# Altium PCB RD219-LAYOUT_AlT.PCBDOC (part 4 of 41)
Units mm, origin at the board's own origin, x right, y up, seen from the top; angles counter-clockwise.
Board outline 209.75 x 159.97 mm, 2 copper layers (TOP, BOTTOM), stack 0 mm thick; 398 components, 199 nets, 1469 pads, 0 vias.
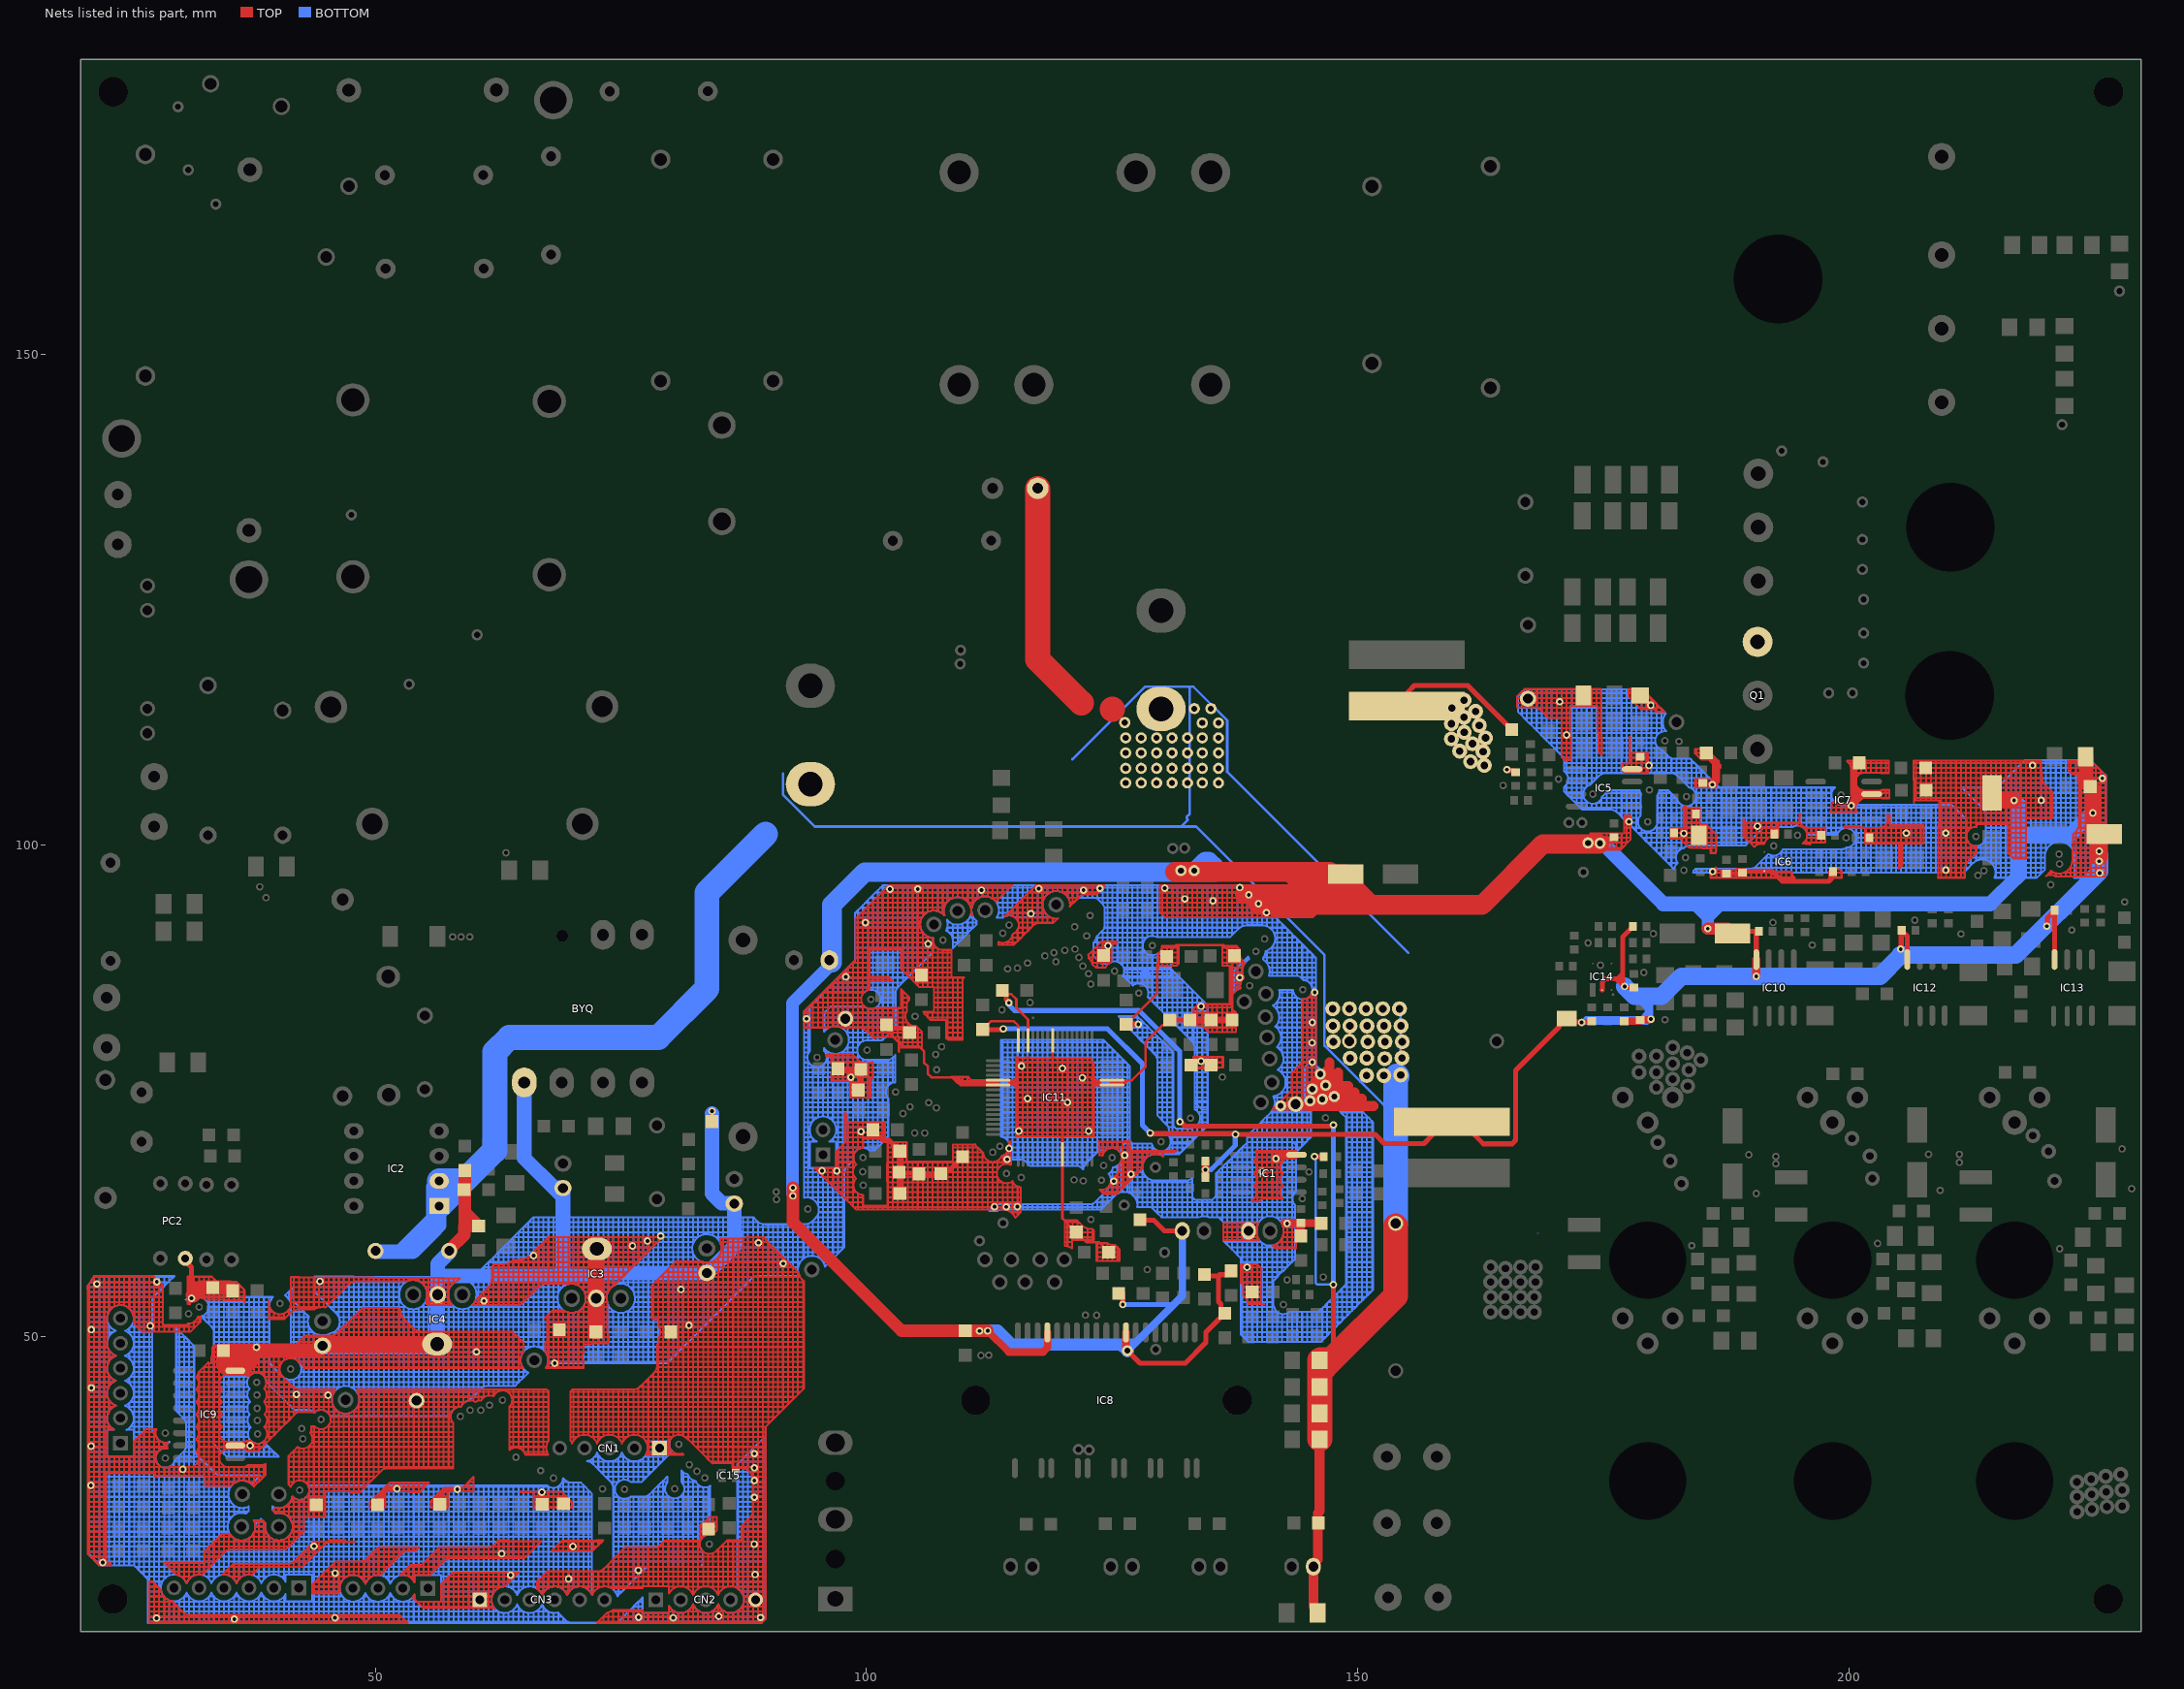
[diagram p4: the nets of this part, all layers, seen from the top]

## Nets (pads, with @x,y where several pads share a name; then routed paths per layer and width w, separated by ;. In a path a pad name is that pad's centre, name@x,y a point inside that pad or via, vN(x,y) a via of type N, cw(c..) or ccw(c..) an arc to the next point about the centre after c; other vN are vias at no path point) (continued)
GND: (continued)
  TOP w0.203: 20.889,33.716 21.397,33.716 ; 20.889,33.716 20.889,34.224 ; 20.889,34.224 pad.@20.889,34.732 ; 20.889,34.224 21.397,34.224 ; pad.@20.889,34.732 pad.@21.397,34.732 ; pad.@20.889,34.732 20.889,35.24 ; 20.889,35.24 20.889,35.748 ; 20.889,35.24 21.397,35.24 ; 20.889,35.748 20.889,36.256 ; 20.889,35.748 21.397,35.748 ; 20.889,36.256 20.889,36.764 ; 20.889,36.256 21.397,36.256 ; 20.889,36.764 20.889,37.272 ; 20.889,36.764 21.397,36.764 ; 20.889,37.272 20.889,37.78 ; 20.889,37.272 21.397,37.272 ; 20.889,37.78 20.889,38.288 ; 20.889,37.78 21.397,37.78 ; 20.889,38.288 pad.@20.889,38.796 ; 20.889,38.288 21.397,38.288 ; pad.@20.889,38.796 pad.@21.397,38.796 ; pad.@20.889,38.796 20.889,39.304 ; 20.889,39.304 20.889,39.812 ; 20.889,39.304 21.397,39.304 ; 20.889,39.812 20.889,40.32 ; 20.889,39.812 21.397,39.812 ; 20.889,40.32 20.889,40.828 ; 20.889,40.32 21.397,40.32 ; 20.889,40.828 20.889,41.336 ; 20.889,40.828 21.397,40.828 ; 20.889,41.336 20.889,41.844 ; 20.889,41.336 21.397,41.336 ; 20.889,41.844 20.889,42.352 ; 20.889,41.844 21.397,41.844 ; 20.889,42.352 20.889,42.86 ; 20.889,42.352 21.397,42.352 ; 20.889,42.86 20.889,43.368 ; 20.889,42.86 21.397,42.86 ; 20.889,43.368 20.889,43.876 ; 20.889,43.368 21.397,43.368 ; 20.889,43.876 21.397,43.876 ; 20.889,43.876 20.889,44.384 ; 20.889,44.384 pad.@20.889,44.892 ; 20.889,44.384 21.397,44.384 ; pad.@20.889,44.892 20.889,45.4 ; pad.@20.889,44.892 pad.@21.397,44.892 ; 20.889,45.4 21.397,45.4 ; 20.889,45.4 20.889,45.908 ; 20.889,45.908 20.889,46.416 ; 20.889,45.908 21.397,45.908 ; 20.889,46.416 20.889,46.924 ; 20.889,46.416 21.397,46.416 ; 20.889,46.924 20.889,47.432 ; 20.889,46.924 21.397,46.924 ; 20.889,47.432 20.889,47.94 ; 20.889,47.432 21.397,47.432 ; 20.889,47.94 21.397,47.94 ; 20.889,47.94 20.889,48.448 ; 20.889,48.448 20.889,48.956 ; 20.889,48.448 21.397,48.448 ; 20.889,48.956 20.889,49.464 ; 20.889,48.956 21.397,48.956 ; 20.889,49.464 21.397,49.464 ; 20.889,49.464 20.889,49.972 ; 20.889,49.972 pad.@20.889,50.48 ; 20.889,49.972 21.397,49.972 ; pad.@20.889,50.48 21.397,50.48 ; pad.@20.889,50.48 pad.@20.889,50.988 ; pad.@20.889,50.988 20.889,51.496 ; pad.@20.889,50.988 21.397,50.988 ; 20.889,51.496 20.889,52.004 ; 20.889,51.496 21.397,51.496 ; 20.889,52.004 21.397,52.004 ; 20.889,52.004 20.889,52.512 ; 20.889,52.512 20.889,53.02 ; 20.889,52.512 21.397,52.512 ; 20.889,53.02 20.889,53.528 ; 20.889,53.02 21.397,53.02 ; 20.889,53.528 21.397,53.528 ; 20.889,53.528 20.889,54.036 ; 20.889,54.036 20.889,54.544 ; 20.889,54.036 21.397,54.036 ; 20.889,54.544 20.889,55.052 ; 20.889,54.544 21.397,54.544 ; 20.889,55.052 20.889,55.369 ; 20.889,55.052 21.397,55.052 ; 20.889,55.369 21.016,55.56 ; 21.016,27.62 21.397,27.62 ; 21.016,27.62 21.397,27.239 ; 21.016,55.56 pad.@21.397,55.56 ; 21.016,55.56 21.441,56.197 22.413,56.191 ; 21.397,27.239 21.397,27.62 ; 21.397,27.239 21.524,27.112 ; 21.397,27.62 21.905,27.62 ; 21.397,27.62 21.397,28.128 ; 21.397,28.128 21.397,28.636 ; 21.397,28.128 21.905,28.128 ; 21.397,28.636 21.397,29.144 ; 21.397,28.636 21.905,28.636 ; 21.397,29.144 21.905,29.144 ; 21.397,29.144 21.397,29.652 ; 21.397,29.652 21.905,29.652 ; 21.397,29.652 21.397,30.16 ; 21.397,30.16 21.397,30.668 ; 21.397,30.16 21.905,30.16 ; 21.397,30.668 21.397,31.176 ; 21.397,30.668 21.905,30.668 ; 21.397,31.176 21.397,31.684 ; 21.397,31.176 21.905,31.176 ; 21.397,31.684 21.905,31.684 ; 21.397,31.684 21.397,32.192 ; 21.397,32.192 21.397,32.7 ; 21.397,32.192 21.905,32.192 ; 21.397,32.7 21.397,33.208 ; 21.397,32.7 21.905,32.7 ; 21.397,33.208 21.397,33.716 ; 21.397,33.208 21.905,33.208 ; 21.397,33.716 21.905,33.716 ; 21.397,33.716 21.397,34.224 ; 21.397,34.224 pad.@21.397,34.732 ; 21.397,34.224 21.905,34.224 ; pad.@21.397,34.732 21.905,34.732 ; pad.@21.397,34.732 21.397,35.24 ; 21.397,35.24 21.905,35.24 ; 21.397,35.24 21.397,35.748 ; 21.397,35.748 21.397,36.256 ; 21.397,35.748 21.905,35.748 ; 21.397,36.256 21.397,36.764 ; 21.397,36.256 21.905,36.256 ; 21.397,36.764 21.397,37.272 ; 21.397,36.764 21.905,36.764 ; 21.397,37.272 21.397,37.78 ; 21.397,37.272 21.905,37.272 ; 21.397,37.78 21.397,38.288 ; 21.397,37.78 21.905,37.78 ; 21.397,38.288 pad.@21.397,38.796 ; 21.397,38.288 21.905,38.288 ; pad.@21.397,38.796 21.905,38.796 ; pad.@21.397,38.796 21.397,39.304 ; 21.397,39.304 21.397,39.812 ; 21.397,39.304 21.905,39.304 ; 21.397,39.812 21.397,40.32 ; 21.397,39.812 21.905,39.812 ; 21.397,40.32 21.397,40.828 ; 21.397,40.32 21.905,40.32 ; 21.397,40.828 21.397,41.336 ; 21.397,40.828 21.905,40.828 ; 21.397,41.336 21.397,41.844 ; 21.397,41.336 21.905,41.336 ; 21.397,41.844 21.397,42.352 ; 21.397,41.844 21.905,41.844 ; 21.397,42.352 21.397,42.86 ; 21.397,42.352 21.905,42.352 ; 21.397,42.86 21.397,43.368 ; 21.397,42.86 21.905,42.86 ; 21.397,43.368 21.397,43.876 ; 21.397,43.368 21.905,43.368 ; 21.397,43.876 21.905,43.876 ; 21.397,43.876 21.397,44.384 ; 21.397,44.384 21.905,44.384 ; 21.397,44.384 pad.@21.397,44.892 ; pad.@21.397,44.892 21.397,45.4 ; pad.@21.397,44.892 21.905,44.892 ; 21.397,45.4 21.905,45.4 ; 21.397,45.4 21.397,45.908 ; 21.397,45.908 21.397,46.416 ; 21.397,45.908 21.905,45.908 ; 21.397,46.416 21.397,46.924 ; 21.397,46.416 21.905,46.416 ; 21.397,46.924 21.397,47.432 ; 21.397,46.924 21.905,46.924 ; 21.397,47.432 21.397,47.94 ; 21.397,47.432 21.905,47.432 ; 21.397,47.94 21.905,47.94 ; 21.397,47.94 21.397,48.448 ; 21.397,48.448 21.397,48.956 ; 21.397,48.448 21.905,48.448 ; 21.397,48.956 21.397,49.464 ; 21.397,48.956 21.905,48.956 ; 21.397,49.464 21.905,49.464 ; 21.397,49.464 21.397,49.972 ; 21.397,49.972 21.397,50.48 ; 21.397,49.972 21.905,49.972 ; 21.397,50.48 21.905,50.48 ; 21.397,50.48 21.397,50.988 ; 21.397,50.988 21.397,51.496 ; 21.397,50.988 21.905,50.988 ; 21.397,51.496 21.397,52.004 ; 21.397,51.496 21.905,51.496 ; 21.397,52.004 21.905,52.004 ; 21.397,52.004 21.397,52.512 ; 21.397,52.512 21.397,53.02 ; 21.397,52.512 21.905,52.512 ; 21.397,53.02 21.397,53.528 ; 21.397,53.02 21.905,53.02 ; 21.397,53.528 21.905,53.528 ; 21.397,53.528 21.397,54.036 ; 21.397,54.036 21.397,54.544 ; 21.397,54.036 21.905,54.036 ; 21.397,54.544 21.397,55.052 ; 21.397,54.544 21.905,54.544 ; 21.397,55.052 pad.@21.397,55.56 ; 21.397,55.052 21.905,55.052 ; pad.@21.397,55.56 21.397,56.068 ; pad.@21.397,55.56 pad.@21.905,55.56 ; 21.397,56.068 21.905,56.068 ; 21.524,27.112 pad.@21.905,27.112 ; 21.524,27.112 21.905,26.731 ; 21.905,26.731 pad.@22.413,26.731 ; 21.905,26.731 pad.@21.905,27.112 ; pad.@21.905,27.112 21.905,27.62 ; pad.@21.905,27.112 pad.@22.413,27.112 ; 21.905,27.62 22.413,27.62 ; 21.905,27.62 21.905,28.128 ; 21.905,28.128 21.905,28.636 ; 21.905,28.128 22.413,28.128 ; 21.905,28.636 21.905,29.144 ; 21.905,28.636 22.413,28.636 ; 21.905,29.144 21.905,29.652 ; 21.905,29.144 22.413,29.144 ; 21.905,29.652 21.905,30.16 ; 21.905,29.652 22.413,29.652 ; 21.905,30.16 21.905,30.668 ; 21.905,30.16 22.413,30.16 ; 21.905,30.668 21.905,31.176 ; 21.905,30.668 22.413,30.668 ; 21.905,31.176 21.905,31.684 ; 21.905,31.176 22.413,31.176 ; 21.905,31.684 21.905,32.192 ; 21.905,31.684 22.413,31.684 ; 21.905,32.192 21.905,32.7 ; 21.905,32.192 22.413,32.192 ; 21.905,32.7 21.905,33.208 ; 21.905,32.7 22.413,32.7 ; 21.905,33.208 21.905,33.716 ; 21.905,33.208 22.413,33.208 ; 21.905,33.716 22.413,33.716 ; 21.905,33.716 21.905,34.224 ; 21.905,34.224 21.905,34.732 ; 21.905,34.224 22.413,34.224 ; 21.905,34.732 22.413,34.732 ; 21.905,34.732 21.905,35.24 ; 21.905,35.24 22.413,35.24 ; 21.905,35.24 21.905,35.748 ; 21.905,35.748 21.905,36.256 ; 21.905,35.748 22.413,35.748 ; 21.905,36.256 21.905,36.764 ; 21.905,36.256 22.413,36.256 ; 21.905,36.764 21.905,37.272 ; 21.905,36.764 22.413,36.764 ; 21.905,37.272 21.905,37.78 ; 21.905,37.272 22.413,37.272 ; 21.905,37.78 21.905,38.288 ; 21.905,37.78 22.413,37.78 ; 21.905,38.288 21.905,38.796 ; 21.905,38.288 22.413,38.288 ; 21.905,38.796 21.905,39.304 ; 21.905,38.796 22.413,38.796 ; 21.905,39.304 21.905,39.812 ; 21.905,39.304 22.413,39.304 ; 21.905,39.812 21.905,40.32 ; 21.905,39.812 22.413,39.812 ; 21.905,40.32 21.905,40.828 ; 21.905,40.32 22.413,40.32 ; 21.905,40.828 21.905,41.336 ; 21.905,40.828 22.413,40.828 ; 21.905,41.336 21.905,41.844 ; 21.905,41.336 22.413,41.336 ; 21.905,41.844 21.905,42.352 ; 21.905,41.844 22.413,41.844 ; 21.905,42.352 21.905,42.86 ; 21.905,42.352 22.413,42.352 ; 21.905,42.86 21.905,43.368 ; 21.905,42.86 22.413,42.86 ; 21.905,43.368 21.905,43.876 ; 21.905,43.368 22.413,43.368 ; 21.905,43.876 22.413,43.876 ; 21.905,43.876 21.905,44.384 ; 21.905,44.384 22.413,44.384 ; 21.905,44.384 21.905,44.892 ; 21.905,44.892 21.905,45.4 ; 21.905,44.892 22.413,44.892 ; 21.905,45.4 21.905,45.908 ; 21.905,45.4 22.413,45.4 ; 21.905,45.908 21.905,46.416 ; 21.905,45.908 22.413,45.908 ; 21.905,46.416 21.905,46.924 ; 21.905,46.416 22.413,46.416 ; 21.905,46.924 21.905,47.432 ; 21.905,46.924 22.413,46.924 ; 21.905,47.432 21.905,47.94 ; 21.905,47.432 22.413,47.432 ; 21.905,47.94 22.413,47.94 ; 21.905,47.94 21.905,48.448 ; 21.905,48.448 21.905,48.956 ; 21.905,48.448 22.413,48.448 ; 21.905,48.956 21.905,49.464 ; 21.905,48.956 22.413,48.956 ; 21.905,49.464 22.413,49.464 ; 21.905,49.464 21.905,49.972 ; 21.905,49.972 21.905,50.48 ; 21.905,49.972 22.413,49.972 ; 21.905,50.48 21.905,50.988 ; 21.905,50.48 22.413,50.48 ; 21.905,50.988 21.905,51.496 ; 21.905,50.988 22.413,50.988 ; 21.905,51.496 21.905,52.004 ; 21.905,51.496 22.413,51.496 ; 21.905,52.004 22.413,52.004 ; 21.905,52.004 21.905,52.512 ; 21.905,52.512 21.905,53.02 ; 21.905,52.512 22.413,52.512 ; 21.905,53.02 21.905,53.528 ; 21.905,53.02 22.413,53.02 ; 21.905,53.528 22.413,53.528 ; 21.905,53.528 21.905,54.036 ; 21.905,54.036 21.905,54.544 ; 21.905,54.036 22.413,54.036 ; 21.905,54.544 21.905,55.052 ; 21.905,54.544 22.413,54.544 ; 21.905,55.052 22.413,55.052 ; 21.905,55.052 pad.@21.905,55.56 ; pad.@21.905,55.56 21.905,56.068 ; pad.@21.905,55.56 22.413,55.56 ; 21.905,56.068 22.413,56.068 ; pad.@22.413,26.731 22.921,26.731 ; pad.@22.413,26.731 pad.@22.413,27.112 ; pad.@22.413,27.112 22.413,27.62 ; pad.@22.413,27.112 pad.@22.609,27.112 ; 22.413,27.62 22.609,27.62 ; 22.413,27.62 22.413,28.128 ; 22.413,28.128 22.413,28.636 ; 22.413,28.128 22.609,28.128 ; 22.413,28.636 22.413,29.144 ; 22.413,28.636 22.609,28.636 ; 22.413,29.144 22.413,29.652 ; 22.413,29.144 22.609,29.144 ; 22.413,29.652 22.413,30.16 ; 22.413,29.652 22.609,29.652 ; 22.413,30.16 22.413,30.668 ; 22.413,30.16 22.609,30.16 ; 22.413,30.668 22.413,31.176 ; 22.413,30.668 22.609,30.668 ; 22.413,31.176 22.413,31.684 ; 22.413,31.176 22.609,31.176 ; 22.413,31.684 22.413,32.192 ; 22.413,31.684 22.609,31.684 ; 22.413,32.192 22.413,32.7 ; 22.413,32.192 22.609,32.192 ; 22.413,32.7 22.413,33.208 ; 22.413,32.7 22.609,32.7 ; 22.413,33.208 22.413,33.716 ; 22.413,33.208 22.609,33.208 ; 22.413,33.716 22.609,33.716 ; 22.413,33.716 22.413,34.224 ; 22.413,34.224 22.413,34.732 ; 22.413,34.224 22.609,34.224 ; 22.413,34.732 22.413,35.24 ; 22.413,34.732 22.577,34.732 ; 22.413,35.24 22.413,35.748 ; 22.413,35.24 22.609,35.24 ; 22.413,35.748 22.413,36.256 ; 22.413,35.748 22.609,35.748 ; 22.413,36.256 22.413,36.764 ; 22.413,36.256 22.921,36.256 ; 22.413,36.764 22.413,37.272 ; 22.413,36.764 22.921,36.764 ; 22.413,37.272 22.413,37.78 ; 22.413,37.272 22.921,37.272 ; 22.413,37.78 22.413,38.288 ; 22.413,37.78 22.921,37.78 ; 22.413,38.288 22.413,38.796 ; 22.413,38.288 22.712,38.288 ; 22.413,38.796 22.413,39.304 ; 22.413,38.796 22.712,38.796 ; 22.413,39.304 22.413,39.812 ; 22.413,39.304 22.712,39.304 ; 22.413,39.812 22.413,40.32 ; 22.413,39.812 22.712,39.812 ; 22.413,40.32 22.413,40.828 ; 22.413,40.32 22.712,40.32 ; 22.413,40.828 22.413,41.336 ; 22.413,40.828 22.921,40.828 ; 22.413,41.336 22.413,41.844 ; 22.413,41.336 22.767,41.336 ; 22.413,41.844 22.413,42.352 ; 22.413,41.844 22.718,41.844 ; 22.413,42.352 22.413,42.86 ; 22.413,42.352 22.871,42.352 ; 22.413,42.86 22.413,43.368 ; 22.413,42.86 22.921,42.86 ; 22.413,43.368 22.413,43.876 ; 22.413,43.368 22.921,43.368 ; 22.413,43.876 22.413,44.384 ; 22.413,43.876 22.765,43.876 ; 22.413,44.384 22.413,44.892 ; 22.413,44.384 22.718,44.384 ; 22.413,44.892 22.413,45.4 ; 22.413,44.892 22.871,44.892 ; 22.413,45.4 22.413,45.908 ; 22.413,45.4 22.921,45.4 ; 22.413,45.908 22.413,46.416 ; 22.413,45.908 22.921,45.908 ; 22.413,46.416 22.413,46.924 ; 22.413,46.416 22.767,46.416 ; 22.413,46.924 22.413,47.432 ; 22.413,46.924 22.718,46.924 ; 22.413,47.432 22.413,47.94 ; 22.413,47.432 22.871,47.432 ; 22.413,47.94 22.921,47.94 ; 22.413,47.94 22.413,48.448 ; 22.413,48.448 22.413,48.956 ; 22.413,48.448 22.921,48.448 ; 22.413,48.956 22.413,49.464 ; 22.413,48.956 22.767,48.956 ; 22.413,49.464 22.413,49.972 ; 22.413,49.464 22.712,49.464 ; 22.413,49.972 22.413,50.48 ; 22.413,49.972 22.712,49.972 ; 22.413,50.48 22.413,50.988 ; 22.413,50.48 22.712,50.48 ; 22.413,50.988 22.413,51.496 ; 22.413,50.988 22.712,50.988 ; 22.413,51.496 22.413,52.004 ; 22.413,51.496 22.712,51.496 ; 22.413,52.004 22.413,52.512 ; 22.413,52.004 22.718,52.004 ; 22.413,52.512 22.413,53.02 ; 22.413,52.512 22.871,52.512 ; 22.413,53.02 22.413,53.528 ; 22.413,53.02 22.921,53.02 ; 22.413,53.528 22.921,53.528 ; 22.413,53.528 22.413,54.036 ; 22.413,54.036 22.413,54.544 ; 22.413,54.036 22.921,54.036 ; 22.413,54.544 22.413,55.052 ; 22.413,54.544 22.921,54.544 ; 22.413,55.052 22.413,55.56 ; 22.413,55.052 22.921,55.052 ; 22.413,55.56 22.921,55.56 ; 22.413,55.56 22.413,56.068 ; 22.413,56.068 22.921,56.068 ; 22.413,56.068 22.413,56.191 ; 22.413,56.191 22.921,56.187 ; 22.577,34.732 cw(c23.429,34.808) 22.609,35.053 ; pad.@22.609,27.112 22.609,27.62 ; pad.@22.609,27.112 22.609,27.003 22.921,27.003 ; 22.609,27.62 22.609,28.128 ; 22.609,28.128 22.609,28.636 ; 22.609,28.636 22.609,29.144 ; 22.609,29.144 22.609,29.652 ; 22.609,29.652 22.609,30.16 ; 22.609,30.16 22.609,30.668 ; 22.609,30.668 22.609,31.176 ; 22.609,31.176 22.609,31.684 ; 22.609,31.684 22.609,32.192 ; 22.609,32.192 22.609,32.7 ; 22.609,32.7 22.609,33.208 ; 22.609,33.208 22.609,33.716 ; 22.609,33.716 22.609,34.224 ; 22.609,35.053 22.609,35.24 ; 22.609,35.24 22.609,35.748 ; 22.609,35.748 22.609,36.111 22.921,36.111 ; 22.712,38.288 22.712,38.796 ; 22.712,38.288 22.712,37.825 22.921,37.825 ; 22.712,38.796 22.712,39.304 ; 22.712,39.304 22.712,39.812 ; 22.712,39.812 22.712,40.32 ; 22.712,40.32 22.712,40.529 22.921,40.529 ; 22.712,49.464 22.712,49.972 ; 22.712,49.972 22.712,50.48 ; 22.712,50.48 22.712,50.988 ; 22.712,50.988 22.712,51.496 ; 22.714,44.315 ccw(c23.429,44.177) 22.765,43.876 ; 22.714,44.315 cw(c24.064,44.257) 22.718,44.384 ; 22.718,41.844 ccw(c24.064,41.717) 22.718,41.835 ccw(c24.064,41.717) 22.767,41.336 ; 22.718,41.844 cw(c24.064,41.717) 22.871,42.352 ; 22.718,44.384 cw(c24.064,44.257) 22.871,44.892 ; 22.718,46.924 ccw(c24.064,46.797) 22.718,46.915 ccw(c24.064,46.797) 22.767,46.416 ; 22.718,46.924 cw(c24.064,46.797) 22.871,47.432 ; 22.718,52.004 ccw(c24.064,51.877) 22.712,51.877 cw(c24.064,51.877) 22.718,52.004 ; 22.718,52.004 cw(c24.064,51.877) 22.871,52.512 ; 22.718,52.004 cw(c24.064,51.877) 22.871,52.512 ; 22.765,48.964 cw(c24.064,49.337) 22.712,49.337 ccw(c24.064,49.337) 22.765,48.964 ; 22.765,48.964 ccw(c24.064,49.337) 22.767,48.956 ; 22.765,48.964 ccw(c24.064,49.337) 22.767,48.956 ; 22.767,41.336 ccw(c24.064,41.717) 22.918,41.001 ccw(c24.064,41.717) 22.921,40.996 ; 22.767,46.416 ccw(c24.064,46.797) 22.918,46.081 ccw(c24.064,46.797) 22.921,46.076 ; 22.767,48.956 ccw(c24.064,49.337) 22.918,48.621 ; 22.767,48.956 ccw(c24.064,49.337) 22.918,48.621 ; 22.871,42.352 cw(c24.064,41.717) 22.918,42.433 cw(c24.064,41.717) 22.921,42.438 ; 22.871,44.892 cw(c24.064,44.257) 22.918,44.973 cw(c24.064,44.257) 22.921,44.978 ; 22.871,47.432 cw(c24.064,46.797) 22.918,47.513 cw(c24.064,46.797) 22.921,47.518 ; 22.871,52.512 cw(c24.064,51.877) 22.918,52.593 ccw(c24.064,51.877) 22.871,52.512 ; 22.918,48.621 ccw(c24.064,49.337) 22.921,48.616 ; 22.918,48.621 ccw(c24.064,49.337) 22.921,48.616 ; 22.921,26.731 22.921,27.003 ; 22.921,26.731 23.152,26.731 ; 22.921,27.003 22.991,27.003 ; 22.921,36.111 22.921,36.256 ; 22.921,36.111 23.429,36.111 ; 22.921,36.256 22.921,36.764 ; 22.921,36.256 23.429,36.256 ; 22.921,36.764 22.921,37.272 ; 22.921,36.764 23.429,36.764 ; 22.921,37.272 22.921,37.78 ; 22.921,37.272 23.429,37.272 ; 22.921,37.78 22.921,37.825 ; 22.921,37.78 23.429,37.78 ; 22.921,37.825 23.429,37.825 ; 22.921,40.529 22.921,40.828 ; 22.921,40.828 23.046,40.828 ; 22.921,40.828 22.921,40.996 ; 22.921,40.996 ccw(c24.064,41.717) 23.044,40.83 ccw(c24.064,41.717) 23.046,40.828 ; 22.921,42.438 cw(c24.064,41.717) 23.343,42.86 ; 22.921,42.438 22.921,42.86 ; 22.921,42.86 22.921,43.368 ; 22.921,42.86 23.343,42.86 ; 22.921,43.368 23.046,43.368 ; 22.921,43.368 22.921,43.536 ; 22.921,43.536 ccw(c24.064,44.257) 23.044,43.37 ccw(c24.064,44.257) 23.046,43.368 ; 22.921,44.978 cw(c24.064,44.257) 23.343,45.4 ; 22.921,44.978 22.921,45.4 ; 22.921,45.4 22.921,45.908 ; 22.921,45.4 23.343,45.4 ; 22.921,45.908 22.921,46.076 ; 22.921,45.908 23.046,45.908 ; 22.921,46.076 ccw(c24.064,46.797) 23.044,45.91 ccw(c24.064,46.797) 23.046,45.908 ; 22.921,47.518 cw(c24.064,46.797) 23.343,47.94 ; 22.921,47.518 22.921,47.94 ; 22.921,47.94 22.921,48.448 ; 22.921,47.94 23.343,47.94 ; 22.921,48.448 23.046,48.448 ; 22.921,48.448 22.921,48.616 ; 22.921,48.616 ccw(c24.064,49.337) 23.044,48.45 ; 22.921,48.616 ccw(c24.064,49.337) 23.044,48.45 ; 22.921,53.02 22.921,53.528 ; 22.921,53.02 23.343,53.02 ; 22.921,53.528 22.921,54.036 ; 22.921,53.528 23.429,53.528 ; 22.921,54.036 22.921,54.544 ; 22.921,54.036 23.429,54.036 ; 22.921,54.544 22.921,55.052 ; 22.921,54.544 23.429,54.544 ; 22.921,55.052 22.921,55.56 ; 22.921,55.052 23.429,55.052 ; 22.921,55.56 22.921,56.068 ; 22.921,55.56 23.429,55.56 ; 22.921,56.068 22.921,56.187 ; 22.921,56.068 23.429,56.068 ; 22.921,56.187 23.429,56.184 ; 22.991,27.003 ccw(c24.011,27.421) 23.152,26.731 ; 22.991,27.003 ccw(c24.011,27.421) 23.152,26.731 ; 22.991,27.003 cw(c24.011,27.421) 22.989,27.008 ccw(c24.011,27.421) 22.991,27.003 ; 23.044,48.45 ccw(c24.064,49.337) 23.046,48.448 ; 23.044,48.45 ccw(c24.064,49.337) 23.046,48.448 ; 23.046,43.368 ccw(c24.064,44.257) 23.429,43.064 ; 23.046,45.908 ccw(c24.064,46.797) 23.429,45.604 ; 23.046,48.448 ccw(c24.064,49.337) 23.429,48.144 ; 23.046,48.448 ccw(c24.064,49.337) 23.429,48.144 ; 23.152,26.731 ccw(c24.011,27.421) 23.155,26.728 cw(c24.011,27.421) 23.152,26.731 ; 23.343,42.86 cw(c24.064,41.717) 23.429,42.91 ; 23.343,45.4 cw(c24.064,44.257) 23.429,45.45 ; 23.343,47.94 cw(c24.064,46.797) 23.429,47.99 ; 23.343,53.02 ccw(c24.064,51.877) 22.93,52.613 cw(c24.064,51.877) 23.343,53.02 ; 23.343,53.02 cw(c24.064,51.877) 23.348,53.023 ; 23.343,53.02 cw(c24.064,51.877) 23.348,53.023 ; 23.348,53.023 cw(c24.064,51.877) 23.429,53.07 ; 23.348,53.023 cw(c24.064,51.877) 23.429,53.07 ; 23.429,36.111 23.429,36.256 ; 23.429,36.111 23.937,36.111 ; 23.429,36.256 23.429,36.764 ; 23.429,36.256 23.937,36.256 ; 23.429,36.764 23.429,37.272 ; 23.429,36.764 23.937,36.764 ; 23.429,37.272 23.429,37.78 ; 23.429,37.272 23.937,37.272 ; 23.429,37.78 23.429,37.825 ; 23.429,37.78 23.937,37.78 ; 23.429,37.825 23.937,37.825 ; 23.429,42.91 cw(c24.064,41.717) 23.601,42.987 cw(c24.064,44.257) 23.429,43.064 ; 23.429,42.91 23.429,43.064 ; 23.429,45.45 cw(c24.064,44.257) 23.601,45.527 cw(c24.064,46.797) 23.429,45.604 ; 23.429,45.45 23.429,45.604 ; 23.429,47.99 cw(c24.064,46.797) 23.601,48.067 ; 23.429,47.99 23.429,48.144 ; 23.429,48.144 ccw(c24.064,49.337) 23.601,48.067 ; 23.429,48.144 ccw(c24.064,49.337) 23.601,48.067 ; 23.429,53.07 cw(c24.064,51.877) 23.937,53.223 ; 23.429,53.07 cw(c24.064,51.877) 23.937,53.223 ; 23.429,53.07 23.429,53.528 ; 23.429,53.528 23.429,54.036 ; 23.429,53.528 23.937,53.528 ; 23.429,54.036 23.429,54.544 ; 23.429,54.036 23.937,54.036 ; 23.429,54.544 23.429,55.052 ; 23.429,54.544 23.937,54.544 ; 23.429,55.052 23.429,55.56 ; 23.429,55.052 23.937,55.052 ; 23.429,55.56 23.429,56.068 ; 23.429,55.56 23.937,55.56 ; 23.429,56.068 23.429,56.184 ; 23.429,56.068 23.937,56.068 ; 23.429,56.184 23.937,56.181 ; 23.937,36.111 23.937,36.256 ; 23.937,36.111 24.445,36.111 ; 23.937,36.256 23.937,36.764 ; 23.937,36.256 24.445,36.256 ; 23.937,36.764 23.937,37.272 ; 23.937,36.764 24.445,36.764 ; 23.937,37.272 23.937,37.78 ; 23.937,37.272 24.445,37.272 ; 23.937,37.78 23.937,37.825 ; 23.937,37.78 24.445,37.78 ; 23.937,37.825 24.445,37.825 ; 23.937,53.223 ccw(c24.064,51.877) 23.923,53.221 cw(c24.064,51.877) 23.937,53.223 ; 23.937,53.223 cw(c24.064,51.877) 23.946,53.223 ccw(c24.064,51.877) 23.937,53.223 ; 23.937,53.223 cw(c24.064,51.877) 24.437,53.176 ; 23.937,53.223 cw(c24.064,51.877) 24.437,53.176 ; 23.937,53.223 23.937,53.528 ; 23.937,53.528 23.937,54.036 ; 23.937,53.528 24.445,53.528 ; 23.937,54.036 23.937,54.544 ; 23.937,54.036 24.445,54.036 ; 23.937,54.544 23.937,55.052 ; 23.937,54.544 24.445,54.544 ; 23.937,55.052 23.937,55.56 ; 23.937,55.052 24.445,55.052 ; 23.937,55.56 23.937,56.068 ; 23.937,55.56 24.445,55.56 ; 23.937,56.068 23.937,56.181 ; 23.937,56.068 24.445,56.068 ; 23.937,56.181 24.445,56.177 ; 24.437,53.176 cw(c24.064,51.877) 24.445,53.174 ; 24.437,53.176 cw(c24.064,51.877) 24.445,53.174 ; 24.445,36.111 24.953,36.111 ; 24.445,36.111 24.445,36.256 ; 24.445,36.256 24.445,36.764 ; 24.445,36.256 24.953,36.256 ; 24.445,36.764 24.445,37.272 ; 24.445,36.764 24.953,36.764 ; 24.445,37.272 24.445,37.78 ; 24.445,37.272 24.953,37.272 ; 24.445,37.78 24.445,37.825 ; 24.445,37.78 24.953,37.78 ; 24.445,37.825 24.953,37.825 ; 24.445,53.174 cw(c24.064,51.877) 24.78,53.023 ; 24.445,53.174 cw(c24.064,51.877) 24.78,53.023 ; 24.445,53.174 24.445,53.528 ; 24.445,53.528 24.445,54.036 ; 24.445,53.528 24.953,53.528 ; 24.445,54.036 24.445,54.544 ; 24.445,54.036 24.953,54.036 ; 24.445,54.544 24.445,55.052 ; 24.445,54.544 24.953,54.544 ; 24.445,55.052 24.445,55.56 ; 24.445,55.052 24.953,55.052 ; 24.445,55.56 24.445,56.068 ; 24.445,55.56 24.953,55.56 ; 24.445,56.068 24.445,56.177 ; 24.445,56.068 24.953,56.068 ; 24.445,56.177 24.953,56.174 ; 24.78,53.023 cw(c24.064,51.877) 24.785,53.02 ; 24.78,53.023 cw(c24.064,51.877) 24.785,53.02 ; 24.785,53.02 cw(c24.064,51.877) 24.951,52.897 ; 24.785,53.02 cw(c24.064,51.877) 24.951,52.897 ; 24.785,53.02 24.953,53.02 ; 24.951,52.897 cw(c24.064,51.877) 24.953,52.895 ; 24.951,52.897 cw(c24.064,51.877) 24.953,52.895 ; 24.953,36.111 24.953,36.256 ; 24.953,36.256 24.953,36.764 ; 24.953,36.256 25.461,36.256 ; 24.953,36.764 24.953,37.272 ; 24.953,36.764 25.461,36.764 ; 24.953,37.272 24.953,37.78 ; 24.953,37.272 25.461,37.272 ; 24.953,37.78 24.953,37.825 ; 24.953,37.78 25.461,37.78 ; 24.953,37.825 25.416,37.825 25.416,38.288 ; 24.953,52.895 cw(c24.064,51.877) 25.257,52.512 ; 24.953,52.895 cw(c24.064,51.877) 25.257,52.512 ; 24.953,52.895 24.953,53.02 ; 24.953,53.02 24.953,53.528 ; 24.953,53.02 25.461,53.02 ; 24.953,53.528 25.461,53.528 ; 24.953,53.528 24.953,54.036 ; 24.953,54.036 24.953,54.544 ; 24.953,54.036 25.461,54.036 ; 24.953,54.544 24.953,55.052 ; 24.953,54.544 25.461,54.544 ; 24.953,55.052 25.461,55.052 ; 24.953,55.052 24.953,55.56 ; 24.953,55.56 25.461,55.56 ; 24.953,55.56 24.953,56.068 ; 24.953,56.068 25.461,56.068 ; 24.953,56.068 24.953,56.174 ; 24.953,56.174 25.969,56.167 ; 25.257,52.512 cw(c24.064,51.877) 25.41,52.004 ; 25.257,52.512 cw(c24.064,51.877) 25.41,52.004 ; 25.257,52.512 25.461,52.512 ; 25.41,52.004 cw(c24.064,51.877) 25.416,51.877 ccw(c24.064,51.877) 25.41,52.004 ; 25.41,52.004 25.461,52.004 ; 25.416,38.288 25.416,38.796 ; 25.416,38.288 25.461,38.288 ; 25.416,38.796 25.461,38.796 ; 25.416,38.796 25.416,39.304 ; 25.416,39.304 25.461,39.304 ; 25.416,39.304 25.416,39.319 25.461,39.364 ; 25.416,51.496 25.461,51.496 ; 25.416,51.496 25.416,51.388 25.461,51.342 ; 25.461,36.111 25.969,36.111 ; 25.461,36.111 25.461,36.256 ; 25.461,36.256 25.461,36.764 ; 25.461,36.256 25.969,36.256 ; 25.461,36.764 25.461,37.272 ; 25.461,36.764 25.969,36.764 ; 25.461,37.272 25.461,37.78 ; 25.461,37.272 25.969,37.272 ; 25.461,37.78 25.461,38.288 ; 25.461,37.78 25.969,37.78 ; 25.461,38.288 25.461,38.796 ; 25.461,38.288 25.969,38.288 ; 25.461,38.796 25.969,38.796 ; 25.461,38.796 25.461,39.304 ; 25.461,39.304 25.969,39.304 ; 25.461,39.304 25.461,39.364 ; 25.461,39.364 25.909,39.812 ; 25.461,51.342 25.461,51.496 ; 25.461,51.342 25.815,50.988 ; 25.461,51.496 25.969,51.496 ; 25.461,51.496 25.461,52.004 ; 25.461,52.004 25.461,52.512 ; 25.461,52.004 25.969,52.004 ; 25.461,52.512 25.461,53.02 ; 25.461,52.512 25.969,52.512 ; 25.461,53.02 25.461,53.528 ; 25.461,53.02 25.969,53.02 ; 25.461,53.528 25.969,53.528 ; 25.461,53.528 25.461,54.036 ; 25.461,54.036 25.461,54.544 ; 25.461,54.036 25.969,54.036 ; 25.461,54.544 25.461,55.052 ; 25.461,54.544 25.969,54.544 ; 25.461,55.052 25.461,55.56 ; 25.461,55.052 25.969,55.052 ; 25.461,55.56 25.969,55.56 ; 25.461,55.56 25.461,56.068 ; 25.461,56.068 25.969,56.068 ; 25.815,50.988 25.969,50.988 ; 25.815,50.988 25.969,50.834 ; 25.909,39.812 25.969,39.812 ; 25.909,39.812 25.969,39.872 ; 25.969,36.111 25.969,36.256 ; 25.969,36.111 26.477,36.111 ; 25.969,36.256 25.969,36.764 ; 25.969,36.256 26.477,36.256 ; 25.969,36.764 25.969,37.272 ; 25.969,36.764 26.477,36.764 ; 25.969,37.272 25.969,37.78 ; 25.969,37.272 26.477,37.272 ; 25.969,37.78 25.969,38.288 ; 25.969,37.78 26.477,37.78 ; 25.969,38.288 25.969,38.796 ; 25.969,38.288 26.477,38.288 ; 25.969,38.796 25.969,39.304 ; 25.969,38.796 26.477,38.796 ; 25.969,39.304 25.969,39.812 ; 25.969,39.304 26.477,39.304 ; 25.969,39.812 26.477,39.812 ; 25.969,39.812 25.969,39.872 ; 25.969,39.872 26.417,40.32 ; 25.969,50.834 25.969,50.988 ; 25.969,50.834 26.275,50.529 26.477,50.529 ; 25.969,50.988 26.477,50.988 ; 25.969,50.988 25.969,51.496 ; 25.969,51.496 26.477,51.496 ; 25.969,51.496 25.969,52.004 ; 25.969,52.004 26.477,52.004 ; 25.969,52.004 25.969,52.512 ; 25.969,52.512 25.969,53.02 ; 25.969,52.512 26.477,52.512 ; 25.969,53.02 25.969,53.528 ; 25.969,53.02 26.477,53.02 ; 25.969,53.528 26.477,53.528 ; 25.969,53.528 25.969,54.036 ; 25.969,54.036 25.969,54.544 ; 25.969,54.036 26.477,54.036 ; 25.969,54.544 25.969,55.052 ; 25.969,54.544 26.477,54.544 ; 25.969,55.052 26.477,55.052 ; 25.969,55.052 25.969,55.56 ; 25.969,55.56 26.477,55.56 ; 25.969,55.56 25.969,56.068 ; 25.969,56.068 26.477,56.068 ; 25.969,56.068 25.969,56.167 ; 25.969,56.167 26.985,56.16 ; 26.417,40.32 26.477,40.38 ; 26.417,40.32 26.477,40.32 ; 26.477,36.111 26.477,36.256 ; 26.477,36.111 26.985,36.111 ; 26.477,36.256 26.477,36.764 ; 26.477,36.256 26.985,36.256 ; 26.477,36.764 26.477,37.272 ; 26.477,36.764 26.985,36.764 ; 26.477,37.272 26.477,37.78 ; 26.477,37.272 26.985,37.272 ; 26.477,37.78 26.477,38.288 ; 26.477,37.78 26.985,37.78 ; 26.477,38.288 26.477,38.796 ; 26.477,38.288 26.985,38.288 ; 26.477,38.796 26.477,39.304 ; 26.477,38.796 26.985,38.796 ; 26.477,39.304 26.477,39.812 ; 26.477,39.304 26.985,39.304 ; 26.477,39.812 26.477,40.32 ; 26.477,39.812 26.985,39.812 ; 26.477,40.32 26.477,40.38 ; 26.477,40.32 26.985,40.32 ; 26.477,40.38 26.704,40.607 26.985,40.607 ; 26.477,50.529 26.477,50.988 ; 26.477,50.529 26.985,50.529 ; 26.477,50.988 26.477,51.496 ; 26.477,50.988 pad.@26.985,50.988 ; 26.477,51.496 26.477,52.004 ; 26.477,51.496 26.985,51.496 ; 26.477,52.004 26.985,52.004 ; 26.477,52.004 26.477,52.512 ; 26.477,52.512 26.477,53.02 ; 26.477,52.512 26.985,52.512 ; 26.477,53.02 26.477,53.528 ; 26.477,53.02 26.985,53.02 ; 26.477,53.528 26.985,53.528 ; 26.477,53.528 26.477,54.036 ; 26.477,54.036 26.477,54.544 ; 26.477,54.036 26.985,54.036 ; 26.477,54.544 26.477,55.052 ; 26.477,54.544 26.985,54.544 ; 26.477,55.052 26.477,55.56 ; 26.477,55.052 26.985,55.052 ; 26.477,55.56 26.985,55.56 ; 26.477,55.56 26.477,56.068 ; 26.477,56.068 26.985,56.068 ; 26.985,21.016 26.985,21.524 ; 26.985,21.016 26.985,20.889 27.493,20.889 ; 26.985,21.016 27.493,21.016 ; 26.985,21.524 26.985,22.032 ; 26.985,21.524 pad.@27.493,21.524 ; 26.985,22.032 26.985,22.54 ; 26.985,22.032 27.493,22.032 ; 26.985,22.54 26.985,23.048 ; 26.985,22.54 27.493,22.54 ; 26.985,23.048 26.985,23.556 ; 26.985,23.048 27.493,23.048 ; 26.985,23.556 26.985,24.064 ; 26.985,23.556 27.493,23.556 ; 26.985,24.064 26.985,24.572 ; 26.985,24.064 27.493,24.064 ; 26.985,24.572 26.985,25.08 ; 26.985,24.572 27.493,24.572 ; 26.985,25.08 26.985,25.121 27.291,25.121 27.332,25.08 ; 26.985,25.08 27.332,25.08 ; 26.985,36.111 27.493,36.111 ; 26.985,36.111 26.985,36.256 ; 26.985,36.256 27.493,36.256 ; 26.985,36.256 26.985,36.764 ; 26.985,36.764 26.985,37.272 ; 26.985,36.764 27.493,36.764 ; 26.985,37.272 26.985,37.78 ; 26.985,37.272 27.493,37.272 ; 26.985,37.78 26.985,38.288 ; 26.985,37.78 27.493,37.78 ; 26.985,38.288 26.985,38.796 ; 26.985,38.288 27.493,38.288 ; 26.985,38.796 27.493,38.796 ; 26.985,38.796 26.985,39.304 ; 26.985,39.304 27.493,39.304 ; 26.985,39.304 26.985,39.812 ; 26.985,39.812 26.985,40.32 ; 26.985,39.812 27.493,39.812 ; 26.985,40.32 26.985,40.607 ; 26.985,40.32 27.493,40.32 ; 26.985,40.607 27.493,40.607 ; 26.985,50.529 27.493,50.529 ; 26.985,50.529 pad.@26.985,50.988 ; pad.@26.985,50.988 27.493,50.988 ; pad.@26.985,50.988 26.985,51.496 ; 26.985,51.496 26.985,52.004 ; 26.985,51.496 27.493,51.496 ; 26.985,52.004 27.493,52.004 ; 26.985,52.004 26.985,52.512 ; 26.985,52.512 26.985,53.02 ; 26.985,52.512 27.493,52.512 ; 26.985,53.02 26.985,53.528 ; 26.985,53.02 27.493,53.02 ; 26.985,53.528 27.493,53.528 ; 26.985,53.528 26.985,54.036 ; 26.985,54.036 26.985,54.544 ; 26.985,54.036 27.493,54.036 ; 26.985,54.544 26.985,55.052 ; 26.985,54.544 27.493,54.544 ; 26.985,55.052 27.493,55.052 ; 26.985,55.052 26.985,55.56 ; 26.985,55.56 pad.@27.493,55.56 ; 26.985,55.56 26.985,56.068 ; 26.985,56.068 27.493,56.068 ; 26.985,56.068 26.985,56.16 ; 27.332,25.08 27.493,24.919 ; 27.493,20.889 27.493,21.016 ; 27.493,20.889 28.001,20.889 ; 27.493,21.016 pad.@27.493,21.524 ; 27.493,21.016 28.001,21.016 ; pad.@27.493,21.524 27.493,22.032 ; pad.@27.493,21.524 pad.@28.001,21.524 ; 27.493,22.032 27.493,22.54 ; 27.493,22.032 28.001,22.032 ; 27.493,22.54 27.493,23.048 ; 27.493,22.54 28.001,22.54 ; 27.493,23.048 27.493,23.556 ; 27.493,23.048 28.001,23.048 ; 27.493,23.556 27.493,24.064 ; 27.493,23.556 28.001,23.556 ; 27.493,24.064 27.493,24.572 ; 27.493,24.064 28.001,24.064 ; 27.493,24.572 27.493,24.919 ; 27.493,24.572 27.84,24.572 ; 27.493,24.919 27.84,24.572 ; 27.493,36.111 27.493,36.256 ; 27.493,36.111 27.602,36.111 27.602,35.748 ; 27.493,36.256 27.493,36.764 ; 27.493,36.256 28.001,36.256 ; 27.493,36.764 27.493,37.272 ; 27.493,36.764 28.001,36.764 ; 27.493,37.272 27.493,37.78 ; 27.493,37.272 27.73,37.272 ; 27.493,37.78 27.493,38.288 ; 27.493,38.288 27.493,38.796 ; 27.493,38.288 27.886,38.288 ; 27.493,38.796 28.001,38.796 ; 27.493,38.796 27.493,39.304 ; 27.493,39.304 28.001,39.304 ; 27.493,39.304 27.493,39.812 ; 27.493,39.812 27.493,40.32 ; 27.493,39.812 27.73,39.812 ; 27.493,40.32 27.493,40.607 ; 27.493,40.32 27.662,40.32 ; 27.493,40.607 27.745,40.607 ccw(c28.636,40.193) 27.662,40.32 ; 27.493,50.529 27.493,50.988 ; 27.493,50.529 28.001,50.529 ; 27.493,50.988 28.001,50.988 ; 27.493,50.988 27.493,51.496 ; 27.493,51.496 28.001,51.496 ; 27.493,51.496 27.493,52.004 ; 27.493,52.004 28.001,52.004 ; 27.493,52.004 27.493,52.512 ; 27.493,52.512 27.493,53.02 ; 27.493,52.512 28.001,52.512 ; 27.493,53.02 27.493,53.528 ; 27.493,53.02 28.001,53.02 ; 27.493,53.528 28.001,53.528 ; 27.493,53.528 27.493,54.036 ; 27.493,54.036 27.493,54.544 ; 27.493,54.036 28.001,54.036 ; 27.493,54.544 27.493,55.052 ; 27.493,54.544 28.001,54.544 ; 27.493,55.052 28.001,55.052 ; 27.493,55.052 pad.@27.493,55.56 ; pad.@27.493,55.56 27.493,56.068 ; pad.@27.493,55.56 pad.@27.987,55.56 ; 27.493,56.068 27.493,56.092 ; 27.493,56.068 27.507,56.068 ; 27.493,56.092 cw(c28.128,56.449) 27.462,56.153 ccw(c28.128,56.449) 27.493,56.092 ; 27.493,56.092 ccw(c28.128,56.449) 27.507,56.068 ; 27.493,56.092 ccw(c28.128,56.449) 27.507,56.068 ; 27.507,56.068 ccw(c28.128,56.449) pad.@27.613,55.934 ; 27.507,56.068 ccw(c28.128,56.449) pad.@27.613,55.934 ; 27.602,35.748 27.602,35.707 27.689,35.707 27.689,35.748 ; 27.602,35.748 27.689,35.748 ; pad.@27.613,55.934 pad.@27.987,55.56 ; 27.662,40.32 ccw(c28.636,40.193) 27.661,40.313 ccw(c28.636,40.193) 27.73,39.812 ; 27.689,35.748 27.689,35.857 28.001,35.857 ; 27.73,37.272 ccw(c28.636,37.653) 27.732,37.269 ccw(c28.636,37.653) 28.001,36.903 ; 27.73,39.812 ccw(c28.636,40.193) 27.732,39.809 ccw(c28.636,40.193) 28.001,39.443 ; 27.84,24.572 28.001,24.411 ; 27.886,38.288 cw(c28.636,37.653) 28.001,38.403 ; pad.@27.987,55.56 pad.@28.001,55.546 ; 28.001,20.889 28.001,21.016 ; 28.001,20.889 28.509,20.889 ; 28.001,21.016 28.509,21.016 ; 28.001,21.016 pad.@28.001,21.524 ; pad.@28.001,21.524 28.001,22.032 ; pad.@28.001,21.524 28.509,21.524 ; 28.001,22.032 28.001,22.54 ; 28.001,22.032 28.509,22.032 ; 28.001,22.54 28.001,23.048 ; 28.001,22.54 28.509,22.54 ; 28.001,23.048 28.001,23.556 ; 28.001,23.048 28.509,23.048 ; 28.001,23.556 28.001,24.064 ; 28.001,23.556 28.507,23.556 ; 28.001,24.064 28.001,24.411 ; 28.001,24.064 28.228,24.064 ; 28.001,35.857 28.001,36.256 ; 28.001,35.857 28.509,35.857 ; 28.001,36.256 28.001,36.764 ; 28.001,36.256 28.509,36.256 ; 28.001,36.764 28.001,36.903 ; 28.001,36.764 28.217,36.764 ; 28.001,36.903 ccw(c28.636,37.653) 28.004,36.9 ccw(c28.636,37.653) 28.217,36.764 ; 28.001,38.403 cw(c28.636,37.653) 28.004,38.406 cw(c28.636,37.653) 28.509,38.627 ; 28.001,38.403 28.001,38.796 ; 28.001,38.796 28.001,39.304 ; 28.001,38.796 28.509,38.796 ; 28.001,39.304 28.001,39.443 ; 28.001,39.304 28.217,39.304 ; 28.001,39.443 ccw(c28.636,40.193) 28.004,39.44 ccw(c28.636,40.193) 28.217,39.304 ; 28.001,50.529 28.001,50.988 ; 28.001,50.529 28.509,50.529 ; 28.001,50.988 28.001,51.496 ; 28.001,50.988 28.509,50.988 ; 28.001,51.496 28.4,51.496 ; 28.001,51.496 28.001,52.004 ; 28.001,52.004 28.4,52.004 ; 28.001,52.004 28.001,52.512 ; 28.001,52.512 28.001,53.02 ; 28.001,52.512 28.4,52.512 ; 28.001,53.02 28.001,53.528 ; 28.001,53.02 28.4,53.02 ; 28.001,53.528 28.4,53.528 ; 28.001,53.528 28.001,54.036 ; 28.001,54.036 28.001,54.544 ; 28.001,54.036 28.4,54.036 ; 28.001,54.544 28.001,55.052 ; 28.001,54.544 28.4,54.544 ; 28.001,55.052 28.4,55.052 ; 28.001,55.052 pad.@28.001,55.546 ; pad.@28.001,55.546 28.4,55.146 28.4,55.052 ; 28.217,36.764 ccw(c28.636,37.653) 28.221,36.762 ccw(c28.636,37.653) 28.509,36.679 ; 28.217,39.304 ccw(c28.636,40.193) 28.509,39.219 ; 28.228,24.064 ccw(c29.525,24.445) 28.507,23.556 ; 28.4,51.496 28.4,52.004 ; 28.4,51.496 28.4,51.184 28.509,51.184 ; 28.4,52.004 28.4,52.512 ; 28.4,52.512 28.4,53.02 ; 28.4,53.02 28.4,53.528 ; 28.4,54.036 28.4,54.544 ; 28.4,54.544 28.4,55.052 ; 28.507,23.556 ccw(c29.525,24.445) 28.509,23.554 ; 28.507,23.556 ccw(c29.525,24.445) 28.509,23.554 ; 28.509,20.889 28.509,21.016 ; 28.509,20.889 29.017,20.889 ; 28.509,21.016 28.509,21.524 ; 28.509,21.016 29.017,21.016 ; 28.509,21.524 28.509,22.032 ; 28.509,21.524 29.017,21.524 ; 28.509,22.032 28.509,22.54 ; 28.509,22.032 29.017,22.032 ; 28.509,22.54 28.509,23.048 ; 28.509,22.54 29.017,22.54 ; 28.509,23.048 29.017,23.048 ; 28.509,23.048 28.509,23.554 ; 28.509,23.554 ccw(c29.525,24.445) 29.017,23.193 ; 28.509,35.857 29.017,35.857 ; 28.509,35.857 28.509,36.256 ; 28.509,36.256 29.017,36.256 ; 28.509,36.256 28.509,36.679 ; 28.509,36.679 ccw(c28.636,37.653) 28.516,36.678 ccw(c28.636,37.653) 29.017,36.747 ; 28.509,38.627 cw(c28.636,37.653) 28.516,38.628 cw(c28.636,37.653) 28.855,38.611 ; 28.509,38.627 28.509,38.796 ; 28.509,38.796 28.809,38.796 ; 28.509,38.796 28.509,39.219 ; 28.509,39.219 ccw(c28.636,40.193) 28.516,39.218 ccw(c28.636,40.193) 28.855,39.235 ; 28.509,50.529 28.509,50.988 ; 28.509,50.529 29.017,50.529 ; 28.509,50.988 29.017,50.988 ; 28.509,50.988 28.509,51.184 ; 28.509,51.184 29.017,51.184 ; 28.809,38.796 ccw(c29.72,38.923) 28.855,38.611 ; 28.809,38.796 cw(c29.72,38.923) 28.855,39.235 ; 29.017,20.889 29.017,21.016 ; 29.017,20.889 29.525,20.889 ; 29.017,21.016 29.017,21.524 ; 29.017,21.016 29.525,21.016 ; 29.017,21.524 29.017,22.032 ; 29.017,21.524 29.525,21.524 ; 29.017,22.032 29.017,22.54 ; 29.017,22.032 29.525,22.032 ; 29.017,22.54 29.017,23.048 ; 29.017,22.54 29.525,22.54 ; 29.017,23.048 29.364,23.048 ; 29.017,23.048 29.017,23.193 ; 29.017,26.511 29.017,26.604 ; 29.017,26.511 29.432,26.096 ; 29.017,26.604 29.525,26.604 ; 29.017,26.604 29.017,27.003 ; 29.017,27.003 29.525,27.003 ; 29.017,35.857 29.525,35.857 ; 29.017,35.857 29.017,36.256 ; 29.017,36.256 29.525,36.256 ; 29.017,36.256 29.017,36.747 ; 29.017,36.747 ccw(c28.636,37.653) 29.055,36.764 ; 29.017,50.529 29.017,50.988 ; 29.017,50.529 29.525,50.529 ; 29.017,50.988 29.017,51.184 ; 29.017,50.988 29.525,50.988 ; 29.017,51.184 29.525,51.184 ; 29.055,36.764 ccw(c28.636,37.653) 29.126,36.801 ; 29.055,36.764 29.486,36.764 ; 29.364,23.048 29.525,22.887 ; 29.432,26.096 29.525,26.096 ; 29.432,26.096 29.525,26.003 ; 29.486,36.764 ccw(c29.72,37.653) 29.525,36.755 ; 29.525,20.889 29.525,21.016 ; 29.525,20.889 30.033,20.889 ; 29.525,21.016 29.525,21.524 ; 29.525,21.016 30.033,21.016 ; 29.525,21.524 29.525,22.032 ; 29.525,21.524 30.033,21.524 ; 29.525,22.032 29.525,22.54 ; 29.525,22.032 30.033,22.032 ; 29.525,22.54 29.525,22.887 ; 29.525,22.54 29.872,22.54 ; 29.525,22.887 29.872,22.54 ; 29.525,26.003 29.525,26.096 ; 29.525,26.003 29.75,25.778 ; 29.525,26.096 30.033,26.096 ; 29.525,26.096 29.525,26.604 ; 29.525,26.604 29.525,27.003 ; 29.525,26.604 30.033,26.604 ; 29.525,27.003 30.033,27.003 ; 29.525,35.857 30.033,35.857 ; 29.525,35.857 29.525,36.256 ; 29.525,36.256 30.033,36.256 ; 29.525,36.256 29.525,36.755 ; 29.525,36.755 ccw(c29.72,37.653) 29.72,36.734 30.033,36.734 ; 29.525,50.529 29.525,50.988 ; 29.525,50.529 30.033,50.529 ; 29.525,50.988 29.525,51.184 ; 29.525,50.988 30.033,50.988 ; 29.525,51.184 30.033,51.184 ; 29.75,25.778 cw(c29.525,24.445) 30.033,25.698 ; 29.872,22.54 30.033,22.379 ; 30.033,20.889 30.541,20.889 ; 30.033,20.889 30.033,21.016 ; 30.033,21.016 30.541,21.016 ; 30.033,21.016 30.033,21.524 ; 30.033,21.524 30.033,22.032 ; 30.033,21.524 30.541,21.524 ; 30.033,22.032 30.033,22.379 ; 30.033,22.032 30.38,22.032 ; 30.033,22.379 30.38,22.032 ; 30.033,25.698 30.033,26.096 ; 30.033,26.096 30.541,26.096 ; 30.033,26.096 30.033,26.604 ; 30.033,26.604 30.033,27.003 ; 30.033,26.604 30.541,26.604 ; 30.033,35.857 30.033,36.256 ; 30.033,36.256 pad.@30.541,36.256 ; 30.033,36.256 30.033,36.734 ; 30.033,36.734 pad.@30.541,36.734 ; 30.033,50.529 30.541,50.529 ; 30.033,50.529 30.033,50.988 ; 30.033,50.988 30.541,50.988 ; 30.033,50.988 30.033,51.184 ; 30.033,51.184 30.541,51.184 ; 30.541,20.889 31.049,20.889 ; 30.541,20.889 30.541,21.016 ; 30.541,21.016 31.049,21.016 ; 30.541,21.016 30.541,21.524 ; 30.541,21.524 31.049,21.524 ; 30.541,21.524 30.541,21.894 ; 30.541,21.894 cw(c31.176,22.794) 30.397,22.015 ccw(c31.176,22.794) 30.541,21.894 ; 30.541,21.894 ccw(c31.176,22.794) 31.049,21.7 ; 30.541,21.894 ccw(c31.176,22.794) 31.049,21.7 ; 30.541,25.336 cw(c29.525,24.445) 30.545,25.332 cw(c29.525,24.445) 30.718,25.08 ; 30.541,25.336 30.541,25.588 ; 30.541,25.588 30.541,26.096 ; 30.541,25.588 31.049,25.588 ; 30.541,26.096 30.541,26.604 ; 30.541,26.096 31.049,26.096 ; 30.541,26.604 30.541,27.003 ; 30.541,26.604 31.049,26.604 ; 30.541,27.003 31.049,27.003 ; 30.541,35.857 31.049,35.857 ; 30.541,35.857 pad.@30.541,36.256 ; pad.@30.541,36.256 31.049,36.256 ; pad.@30.541,36.256 pad.@30.541,36.734 ; pad.@30.541,36.734 31.049,36.734 ; 30.541,50.529 31.049,50.529 ; 30.541,50.529 30.541,50.988 ; 30.541,50.988 31.049,50.988 ; 30.541,50.988 30.541,51.184 ; 30.541,51.184 30.904,51.184 30.904,51.353 ; 30.718,25.08 cw(c29.525,24.445) 30.795,24.908 cw(c32.065,24.445) 30.872,25.08 ; 30.718,25.08 30.872,25.08 ; 30.904,51.353 ccw(c31.001,52.33) 31.049,51.349 ; 30.904,53.308 cw(c31.001,52.33) 31.049,53.312 ; 30.904,53.308 30.904,53.528 ; 30.904,53.528 31.049,53.528 ; 30.904,54.036 30.904,54.544 ; 30.904,54.036 pad.@31.049,54.036 ; 30.904,54.544 31.049,54.544 ; 30.904,54.544 30.904,55.052 ; 30.904,55.052 30.904,55.56 ; 30.904,55.052 31.049,55.052 ; 30.904,55.56 31.049,55.56 ; 30.904,55.56 30.904,56.068 ; 30.904,56.068 31.049,56.068 ; 30.904,56.068 30.904,56.134 31.303,56.132 31.557,56.13 ; 31.049,20.889 31.557,20.889 ; 31.049,20.889 31.049,21.016 ; 31.049,21.016 31.557,21.016 ; 31.049,21.016 31.049,21.524 ; 31.049,21.524 31.557,21.524 ; 31.049,21.524 31.049,21.7 ; 31.049,21.7 ccw(c31.176,22.794) 31.176,21.692 ; 31.049,21.7 ccw(c31.176,22.794) 31.176,21.692 ; 31.049,25.588 31.049,26.096 ; 31.049,25.588 31.344,25.588 ; 31.049,26.096 31.049,26.604 ; 31.049,26.096 31.557,26.096 ; 31.049,26.604 31.049,27.003 ; 31.049,26.604 31.557,26.604 ; 31.049,27.003 31.557,27.003 ; 31.049,35.857 31.557,35.857 ; 31.049,35.857 31.049,36.256 ; 31.049,36.256 31.049,36.734 ; 31.049,36.256 31.557,36.256 ; 31.049,36.734 31.117,36.734 ccw(c31.117,37.653) 31.35,36.764 ; 31.049,50.529 31.049,50.988 ; 31.049,50.529 31.208,50.529 31.557,50.878 ; 31.049,50.988 31.557,50.988 ; 31.049,50.988 31.049,51.349 ; 31.049,51.349 ccw(c31.001,52.33) 31.52,51.496 ; 31.049,53.312 31.049,53.528 ; 31.049,53.528 31.227,53.528 ; 31.049,53.528 pad.@31.049,54.036 ; pad.@31.049,54.036 31.049,54.544 ; pad.@31.049,54.036 31.303,54.036 pad.@31.557,54.036 ; 31.049,54.544 31.049,55.052 ; 31.049,54.544 31.303,54.544 31.557,54.544 ; 31.049,55.052 31.049,55.56 ; 31.049,55.052 31.303,55.052 31.557,55.052 ; 31.049,55.56 31.303,55.56 31.557,55.56 ; 31.049,55.56 31.049,56.068 ; 31.049,56.068 31.303,56.068 31.557,56.068 ; 31.176,21.692 31.557,21.692 ; 31.227,53.528 cw(c32.071,53.026) pad.@31.557,53.863 ; 31.344,25.588 cw(c32.065,24.445) 31.349,25.591 cw(c32.065,24.445) 31.557,25.697 ; 31.35,36.764 ccw(c31.117,37.653) 31.354,36.765 ccw(c31.117,37.653) 31.557,36.846 ; 31.35,36.764 31.557,36.764 ; 31.52,51.496 ccw(c31.001,52.33) 31.557,51.52 ; 31.52,51.496 31.557,51.496 ; 31.557,20.889 31.557,21.016 ; 31.557,20.889 32.065,20.889 ; 31.557,21.016 31.557,21.524 ; 31.557,21.016 32.065,21.016 ; 31.557,21.524 31.557,21.692 ; 31.557,21.524 32.065,21.524 ; 31.557,21.692 32.065,21.692 ; 31.557,25.697 cw(c32.065,24.445) 31.559,25.698 cw(c32.065,24.445) 32.065,25.797 ; 31.557,25.698 31.557,26.096 ; 31.557,26.096 31.557,26.604 ; 31.557,26.096 32.065,26.096 ; 31.557,26.604 31.557,27.003 ; 31.557,26.604 32.065,26.604 ; 31.557,27.003 32.065,27.003 ; 31.557,35.857 32.065,35.857 ; 31.557,35.857 31.557,36.256 ; 31.557,36.256 31.557,36.764 ; 31.557,36.256 32.065,36.256 ; 31.557,36.764 32.065,36.764 ; 31.557,36.764 31.557,36.846 ; 31.557,36.846 ccw(c31.117,37.653) 31.562,36.849 ccw(c31.117,37.653) 31.953,37.272 ; 31.557,50.878 31.667,50.988 ; 31.557,50.878 31.557,50.988 ; 31.557,50.988 31.557,51.496 ; 31.557,50.988 31.667,50.988 ; 31.557,51.496 32.065,51.496 ; 31.557,51.496 31.557,51.52 ; 31.557,51.52 ccw(c31.001,52.33) 31.928,52.004 ; pad.@31.557,53.863 cw(c32.071,53.026) 32.065,54.008 ; pad.@31.557,53.863 pad.@31.557,54.036 ; pad.@31.557,54.036 31.557,54.332 31.557,54.544 ; pad.@31.557,54.036 32.065,54.036 ; 31.557,54.544 31.557,55.052 ; 31.557,54.544 31.769,54.544 32.065,54.544 ; 31.557,55.052 31.557,55.56 ; 31.557,55.052 32.065,55.052 ; 31.557,55.56 32.065,55.56 ; 31.557,55.56 31.557,56.068 ; 31.557,56.068 32.065,56.068 ; 31.557,56.068 31.557,56.13 ; 31.557,56.13 32.573,56.123 ; 31.667,50.988 32.065,51.386 ; 31.781,38.288 cw(c31.117,37.653) 32.027,37.78 ; 31.781,38.288 ccw(c31.117,38.923) 32.027,38.796 ; 31.781,38.288 32.065,38.288 ; 31.781,39.558 cw(c31.117,38.923) 31.953,39.304 ; 31.781,40.828 cw(c31.117,40.193) 32.027,40.32 ; 31.781,40.828 ccw(c31.117,41.463) 32.027,41.336 ; 31.781,40.828 32.065,40.828 ; 31.781,43.368 cw(c31.117,42.733) 32.027,42.86 ; 31.781,43.368 ccw(c31.117,44.003) 32.027,43.876 ; 31.781,43.368 32.065,43.368 ; 31.781,44.638 cw(c31.117,44.003) 31.953,44.384 ; 31.781,45.908 cw(c31.117,45.273) 32.027,45.4 ; 31.781,45.908 32.065,45.908 ; 31.928,52.004 32.065,52.004 ; 31.953,37.272 ccw(c31.117,37.653) 31.956,37.279 ccw(c31.117,37.653) 32.036,37.653 ccw(c31.117,37.653) 32.027,37.78 ; 31.953,37.272 32.065,37.272 ; 31.953,39.304 cw(c31.117,38.923) 31.963,39.282 cw(c31.117,38.923) 32.036,38.923 cw(c31.117,38.923) 32.027,38.796 ; 31.953,39.304 32.065,39.304 ; 31.953,41.844 cw(c31.117,41.463) 31.956,41.837 cw(c31.117,41.463) 32.036,41.463 cw(c31.117,41.463) 32.027,41.336 ; 31.953,41.844 32.065,41.844 ; 31.953,44.384 cw(c31.117,44.003) 31.963,44.362 cw(c31.117,44.003) 32.036,44.003 cw(c31.117,44.003) 32.027,43.876 ; 31.953,44.384 32.065,44.384 ; 32.027,37.78 32.065,37.78 ; 32.027,38.796 32.065,38.796 ; 32.027,40.32 32.065,40.32 ; 32.027,41.336 32.065,41.336 ; 32.027,42.86 32.065,42.86 ; 32.027,43.876 32.065,43.876 ; 32.027,45.4 32.065,45.4 ; 32.036,46.416 32.065,46.445 ; 32.036,46.416 32.065,46.416 ; 32.065,20.889 32.065,21.016 ; 32.065,20.889 32.573,20.889 ; 32.065,21.016 32.065,21.524 ; 32.065,21.016 32.573,21.016 ; 32.065,21.524 32.065,21.692 ; 32.065,21.524 32.573,21.524 ; 32.065,21.692 32.573,21.692 ; 32.065,25.797 32.065,26.096 ; 32.065,26.096 32.573,26.096 ; 32.065,26.096 32.065,26.604 ; 32.065,26.604 32.065,27.003 ; 32.065,26.604 32.573,26.604 ; 32.065,27.003 32.573,27.003 ; 32.065,35.857 32.573,35.857 ; 32.065,35.857 32.065,36.256 ; 32.065,36.256 32.065,36.764 ; 32.065,36.256 32.573,36.256 ; 32.065,36.764 32.065,37.272 ; 32.065,36.764 32.573,36.764 ; 32.065,37.272 32.065,37.78 ; 32.065,37.272 32.573,37.272 ; 32.065,37.78 32.065,38.288 ; 32.065,37.78 32.573,37.78 ; 32.065,38.288 32.065,38.796 ; 32.065,38.288 32.573,38.288 ; 32.065,38.796 32.065,39.304 ; 32.065,38.796 32.573,38.796 ; 32.065,39.304 32.065,39.812 ; 32.065,39.304 32.573,39.304 ; 32.065,39.812 32.065,40.32 ; 32.065,39.812 32.573,39.812 ; 32.065,40.32 32.065,40.828 ; 32.065,40.32 32.573,40.32 ; 32.065,40.828 32.573,40.828 ; 32.065,40.828 32.065,41.336 ; 32.065,41.336 32.573,41.336 ; 32.065,41.336 32.065,41.844 ; 32.065,41.844 32.065,42.352 ; 32.065,41.844 32.573,41.844 ; 32.065,42.352 32.065,42.86 ; 32.065,42.352 32.573,42.352 ; 32.065,42.86 32.065,43.368 ; 32.065,42.86 32.573,42.86 ; 32.065,43.368 32.573,43.368 ; 32.065,43.368 32.065,43.876 ; 32.065,43.876 32.573,43.876 ; 32.065,43.876 32.065,44.384 ; 32.065,44.384 32.065,44.892 ; 32.065,44.384 32.573,44.384 ; 32.065,44.892 32.065,45.4 ; 32.065,44.892 32.573,44.892 ; 32.065,45.4 32.573,45.4 ; 32.065,45.4 32.065,45.908 ; 32.065,45.908 32.573,45.908 ; 32.065,45.908 32.065,46.416 ; 32.065,46.416 32.573,46.416 ; 32.065,46.416 32.065,46.445 ; 32.065,46.445 32.544,46.924 ; 32.065,51.386 32.065,51.496 ; 32.065,51.496 32.065,52.004 ; 32.065,51.496 32.182,51.496 ; 32.065,52.004 32.21,52.004 ; 32.065,52.004 32.065,52.043 ; 32.065,52.043 ccw(c32.071,53.026) 32.21,52.053 ; 32.065,54.008 cw(c32.071,53.026) 32.573,53.87 ; 32.065,54.008 32.065,54.036 ; 32.065,54.036 32.065,54.544 ; 32.065,54.036 32.573,54.036 ; 32.065,54.544 32.065,54.84 32.065,55.052 ; 32.065,54.544 32.573,54.544 ; 32.065,55.052 32.065,55.56 ; 32.065,55.052 32.573,55.052 ; 32.065,55.56 32.065,56.068 ; 32.065,55.56 32.573,55.56 ; 32.065,56.068 32.573,56.068 ; 32.182,51.496 ccw(c33.056,50.466) 32.101,51.421 cw(c33.056,50.466) 32.182,51.496 ; 32.182,51.496 cw(c33.056,50.466) 32.206,51.516 ccw(c33.056,50.466) 32.182,51.496 ; 32.21,52.004 32.21,52.053 ; 32.544,46.924 32.573,46.924 ; 32.544,46.924 32.573,46.953 ; 32.573,20.889 32.573,21.016 ; 32.573,20.889 33.081,20.889 ; 32.573,21.016 32.573,21.524 ; 32.573,21.016 33.081,21.016 ; 32.573,21.524 32.573,21.692 ; 32.573,21.524 33.081,21.524 ; 32.573,21.692 33.081,21.692 ; 32.573,25.983 32.686,26.096 ; 32.573,25.983 32.573,26.096 ; 32.573,26.096 32.573,26.604 ; 32.573,26.096 32.686,26.096 ; 32.573,26.604 33.081,26.604 ; 32.573,26.604 32.573,27.003 ; 32.573,27.003 32.631,27.003 32.631,27.112 ; 32.573,35.857 32.682,35.857 32.682,35.748 ; 32.573,35.857 32.573,36.256 ; 32.573,36.256 32.573,36.764 ; 32.573,36.256 33.081,36.256 ; 32.573,36.764 32.573,37.272 ; 32.573,36.764 33.081,36.764 ; 32.573,37.272 32.573,37.78 ; 32.573,37.272 33.081,37.272 ; 32.573,37.78 32.573,38.288 ; 32.573,37.78 33.081,37.78 ; 32.573,38.288 32.573,38.796 ; 32.573,38.288 33.081,38.288 ; 32.573,38.796 32.573,39.304 ; 32.573,38.796 33.081,38.796 ; 32.573,39.304 32.573,39.812 ; 32.573,39.304 33.081,39.304 ; 32.573,39.812 32.573,40.32 ; 32.573,39.812 33.081,39.812 ; 32.573,40.32 32.573,40.828 ; 32.573,40.32 33.081,40.32 ; 32.573,40.828 33.081,40.828 ; 32.573,40.828 32.573,41.336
